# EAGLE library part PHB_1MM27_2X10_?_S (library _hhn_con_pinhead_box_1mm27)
Pin Header Box-Type, 1.27mm/0.5"/50mil Pitch, 2x10 Circuits, single gates in schematic Note: see library description for an important note about THT-version
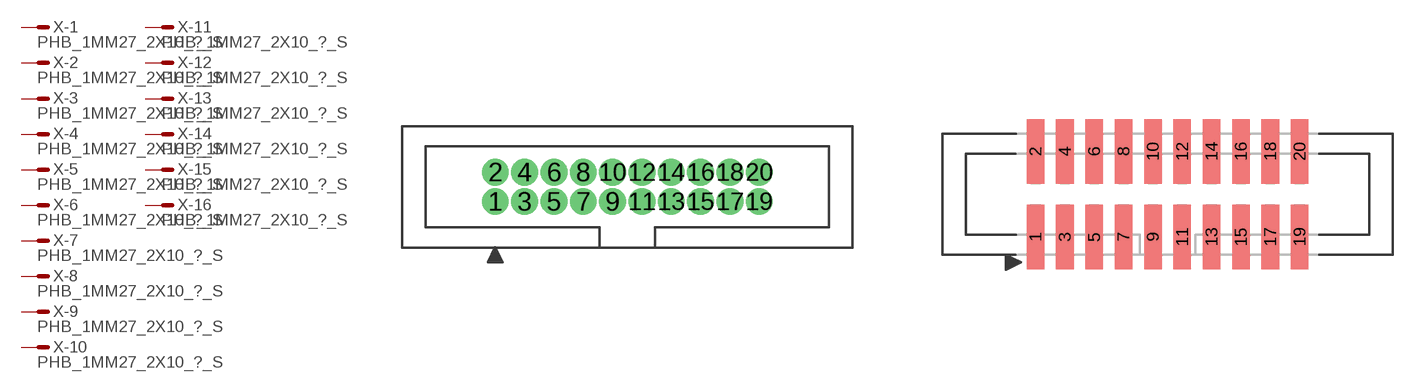
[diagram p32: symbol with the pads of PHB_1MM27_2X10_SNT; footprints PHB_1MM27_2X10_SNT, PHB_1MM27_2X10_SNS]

Designator prefix X; gates -1=M -2=M -3=M -4=M -5=M -6=M -7=M -8=M -9=M -10=M -11=M -12=M -13=M -14=M -15=M -16=M -17=M -18=M -19=M -20=M

## PHB_1MM27_2X10_SNT_S  [PHB_1MM27_2X10_SNT]
1  -1:S  pas
2  -2:S  pas
3  -3:S  pas
4  -4:S  pas
5  -5:S  pas
6  -6:S  pas
7  -7:S  pas
8  -8:S  pas
9  -9:S  pas
10  -10:S  pas
11  -11:S  pas
12  -12:S  pas
13  -13:S  pas
14  -14:S  pas
15  -15:S  pas
16  -16:S  pas
17  -17:S  pas
18  -18:S  pas
19  -19:S  pas
20  -20:S  pas

## PHB_1MM27_2X10_SNS_S  [PHB_1MM27_2X10_SNS]
Pads as for PHB_1MM27_2X10_SNT

## Footprint PHB_1MM27_2X10_SNT (pad centres in mm)
Pin Header Box-Type, 1.27mm Pitch, 2x10 circuits, Straight, No Locking, THT Important Note: Diameter in this lbr is set to a specific value (NOT 'auto' = 0), this is ignored by actual eagle versions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
drill 0.65 pad 1 round: 1 -5.715,-0.635; 2 -5.715,0.635; 3 -4.445,-0.635; 4 -4.445,0.635; 5 -3.175,-0.635; 6 -3.175,0.635; 7 -1.905,-0.635; 8 -1.905,0.635; 9 -0.635,-0.635; 10 -0.635,0.635; 11 0.635,-0.635; 12 0.635,0.635; 13 1.905,-0.635; 14 1.905,0.635; 15 3.175,-0.635; 16 3.175,0.635; 17 4.445,-0.635; 18 4.445,0.635; 19 5.715,-0.635; 20 5.715,0.635

## Footprint PHB_1MM27_2X10_SNS (pad centres in mm)
Pin Header Box-Type, 1.27mm Pitch, 2x10 circuits, Straight, No Locking, SMT
smd 0.76 x 2.8: 1 -5.715,-1.85; 2 -5.715,1.85; 3 -4.445,-1.85; 4 -4.445,1.85; 5 -3.175,-1.85; 6 -3.175,1.85; 7 -1.905,-1.85; 8 -1.905,1.85; 9 -0.635,-1.85; 10 -0.635,1.85; 11 0.635,-1.85; 12 0.635,1.85; 13 1.905,-1.85; 14 1.905,1.85; 15 3.175,-1.85; 16 3.175,1.85; 17 4.445,-1.85; 18 4.445,1.85; 19 5.715,-1.85; 20 5.715,1.85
